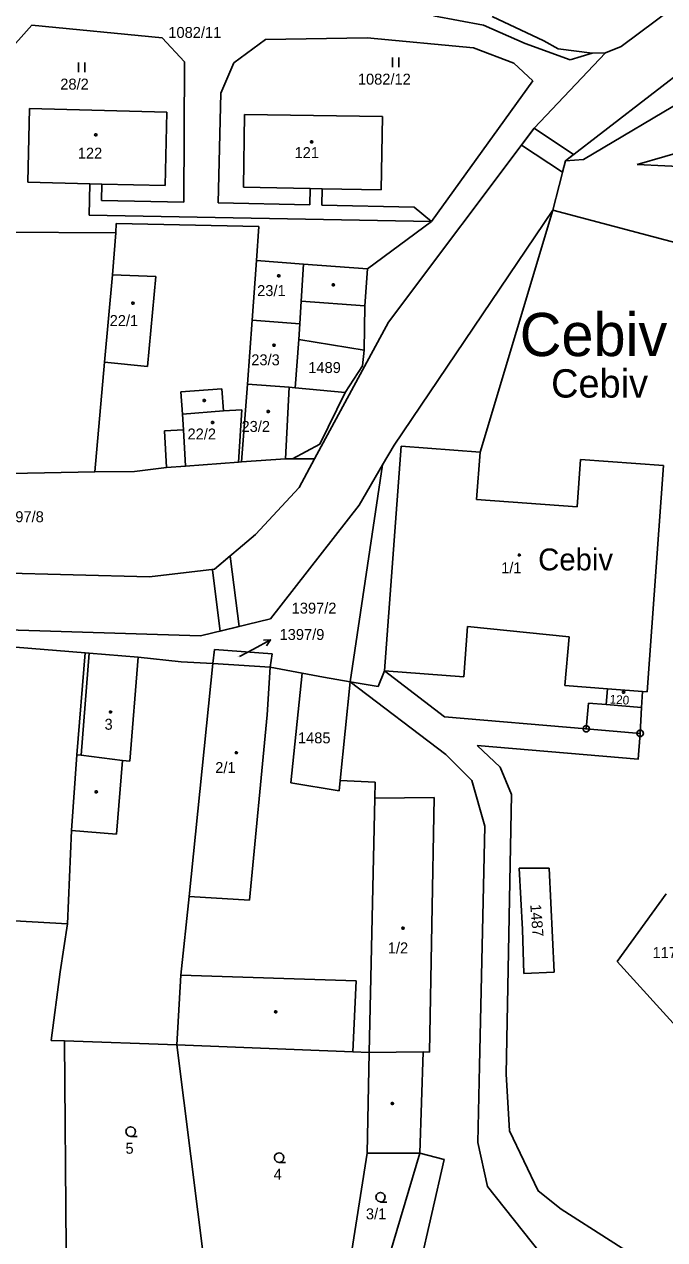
# Model space of a CAD drawing. Extents: x -850689 to -847910, y -1058374 to -1054747.
# Drawn here: x -849425.6 to -849326.1, y -1056444.2 to -1056255.5 of the extents above; entities that cross this region are included whole.
import ezdxf

# ---------------------------------------------------------------- set-up
doc = ezdxf.new("R2010")
doc.units = 0
for name, color, linetype in [('KN_BREMENA', 7, 'Continuous'), ('KN_HRANICE', 7, 'Continuous'), ('KN_KULTURY', 7, 'Continuous'), ('KN_MEZNIKY', 7, 'Continuous'), ('KN_PARCELY', 7, 'Continuous'), ('KN_SLUCKY', 7, 'Continuous'), ('KN_STAVEBNI', 7, 'Continuous')]:
    doc.layers.add(name, color=color, linetype=linetype)

# ---------------------------------------------------------------- blocks, each defined once
blk = doc.blocks.new('304')
blk.add_lwpolyline([(0, 0), (-0.38, 0.1), (-0.65, 0.37), (-0.75, 0.74), (-0.65, 1.11), (-0.38, 1.38), (-0.01, 1.48), (0.36, 1.38), (0.63, 1.11), (0.73, 0.73), (0.63, 0.35), (0.36, 0.08), (-0.02, -0.02), (0.98, -0.02)])
blk = doc.blocks.new('306')
for p, q in [((-0.5, 1.5), (-0.5, 0)), ((0.5, 0), (0.5, 1.5))]:
    blk.add_line(p, q)
blk = doc.blocks.new('10292')
blk.add_line((0, 3), (0, 0))
blk.add_lwpolyline([(-0.5, 2), (0, 3), (0.5, 2)])
blk = doc.blocks.new('402')
blk.add_lwpolyline([(0.09, 0.15), (0.18, 0), (0.09, -0.15), (-0.09, -0.15), (-0.18, 0), (-0.09, 0.15), (0.09, 0.15)])
blk = doc.blocks.new('105')
blk.add_line((-0.12, 0), (0.12, 0))
blk.add_lwpolyline([(0.15, 0.48), (0.4, 0.3), (0.5, 0.01), (0.4, -0.28), (0.15, -0.46), (-0.16, -0.46), (-0.41, -0.28), (-0.51, 0.01), (-0.41, 0.3), (-0.16, 0.48), (0.15, 0.48)])

msp = doc.modelspace()

# ---------------------------------------------------------------- linework, layer by layer
at = {"layer": 'KN_BREMENA'}
for points in [[(-849342, -1056278.44), (-849348.38, -1056274.23), (-849346.41, -1056271.62), (-849340.27, -1056275.67), (-849341.54, -1056276.65)], [(-849395.16, -1056349.69), (-849396.35, -1056340.23), (-849396.37, -1056340.1), (-849396.03, -1056340.06), (-849393.6, -1056338), (-849393.54, -1056338.48), (-849392.22, -1056348.98)]]:
    msp.add_lwpolyline(points, close=True, dxfattribs=at)
for points in [[(-849354.04, -1056379.97), (-849356.06, -1056372.86), (-849360.12, -1056368.85), (-849374.96, -1056357.55), (-849370.64, -1056358.28), (-849369.64, -1056355.88), (-849360.34, -1056362.98)], [(-849360.34, -1056362.98), (-849338.31, -1056364.85), (-849329.95, -1056365.57), (-849330.23, -1056369.56), (-849355.23, -1056367.43)], [(-849355.23, -1056367.43), (-849351.69, -1056370.82), (-849349.93, -1056375.07), (-849350.77, -1056418.49), (-849350.24, -1056427.3), (-849345.77, -1056436.61), (-849342.23, -1056439.43), (-849327.01, -1056449.14), (-849298.02, -1056468.19), (-849284.6, -1056463.96), (-849270.77, -1056447.7), (-849287.91, -1056435.18), (-849282.02, -1056427.2), (-849264.01, -1056440.34), (-849244.44, -1056411.59), (-849258.75, -1056401.09), (-849252.32, -1056392.28), (-849210.21, -1056427.21)], [(-849305.2, -1056487.17), (-849298.59, -1056476.85), (-849345.45, -1056446.21), (-849353.67, -1056435.91), (-849355.13, -1056429.06), (-849354.9, -1056417.2), (-849354.04, -1056379.97)]]:
    msp.add_lwpolyline(points, dxfattribs=at)
at = {"layer": 'KN_HRANICE'}
for p, q in [((-849324.78, -1056252.85), (-849332.91, -1056258.92)), ((-849362.03, -1056254.15), (-849354.27, -1056255.62)), ((-849344.89, -1056258.04), (-849352.94, -1056254.24)), ((-849424.4, -1056255.6), (-849428.61, -1056260.33)), ((-849404.18, -1056257.55), (-849424.4, -1056255.6)), ((-849354.27, -1056255.62), (-849347.82, -1056258.48)), ((-849400.7, -1056261.28), (-849404.18, -1056257.55)), ((-849388.12, -1056257.84), (-849393.05, -1056261.45)), ((-849372.35, -1056257.55), (-849388.12, -1056257.84)), ((-849355.83, -1056259.12), (-849372.35, -1056257.55)), ((-849349.55, -1056261.51), (-849355.83, -1056259.12)), ((-849347.82, -1056258.48), (-849340.83, -1056261.01)), ((-849342.67, -1056259.27), (-849344.89, -1056258.04)), ((-849335.32, -1056259.89), (-849332.91, -1056258.92)), ((-849335.32, -1056259.89), (-849346.41, -1056271.62)), ((-849337.4, -1056259.96), (-849342.67, -1056259.27)), ((-849340.83, -1056261.01), (-849337.4, -1056259.96)), ((-849338.74, -1056276.48), (-849311.64, -1056260.39)), ((-849335.32, -1056259.89), (-849337.4, -1056259.96)), ((-849400.7, -1056261.28), (-849400.81, -1056283.1)), ((-849393.05, -1056261.45), (-849395.08, -1056266.18)), ((-849346.61, -1056264.23), (-849349.55, -1056261.51)), ((-849341.54, -1056276.65), (-849321.82, -1056261.46)), ((-849346.61, -1056264.23), (-849362.36, -1056286.11)), ((-849395.08, -1056266.18), (-849395.45, -1056283.21)), ((-849425.04, -1056279.98), (-849424.78, -1056268.57)), ((-849424.78, -1056268.57), (-849403.43, -1056269.1)), ((-849403.43, -1056269.1), (-849403.71, -1056280.52)), ((-849391.56, -1056280.75), (-849391.39, -1056269.46)), ((-849391.39, -1056269.46), (-849369.95, -1056269.77)), ((-849369.95, -1056269.77), (-849370.17, -1056281.18)), ((-849330.43, -1056277.22), (-849303.93, -1056269.58)), ((-849346.41, -1056271.62), (-849369.03, -1056301.74)), ((-849341.54, -1056276.65), (-849343.49, -1056284.33)), ((-849341.54, -1056276.65), (-849338.74, -1056276.48)), ((-849330.43, -1056277.22), (-849321.06, -1056277.69)), ((-849415.41, -1056280.22), (-849425.04, -1056279.98)), ((-849415.48, -1056285.11), (-849415.41, -1056280.22)), ((-849413.55, -1056280.27), (-849415.41, -1056280.22)), ((-849413.61, -1056282.82), (-849413.55, -1056280.27)), ((-849403.71, -1056280.52), (-849413.55, -1056280.27)), ((-849381.2, -1056280.96), (-849391.56, -1056280.75)), ((-849381.26, -1056283.52), (-849381.2, -1056280.96)), ((-849379.31, -1056281), (-849381.2, -1056280.96)), ((-849379.36, -1056283.57), (-849379.31, -1056281)), ((-849370.17, -1056281.18), (-849379.31, -1056281)), ((-849413.61, -1056282.82), (-849400.81, -1056283.1)), ((-849395.45, -1056283.21), (-849381.26, -1056283.52)), ((-849379.36, -1056283.57), (-849365.06, -1056283.87)), ((-849415.48, -1056285.11), (-849362.36, -1056286.11)), ((-849368.16, -1056320.82), (-849343.49, -1056284.33)), ((-849365.06, -1056283.87), (-849362.36, -1056286.11)), ((-849343.49, -1056284.33), (-849354.8, -1056321.89)), ((-849299.89, -1056295.86), (-849343.49, -1056284.33)), ((-849411.31, -1056286.39), (-849411.38, -1056287.83)), ((-849389.17, -1056286.88), (-849411.31, -1056286.39)), ((-849389.17, -1056286.88), (-849389.51, -1056292.14)), ((-849372.28, -1056293.44), (-849362.36, -1056286.11)), ((-849429.11, -1056287.73), (-849411.38, -1056287.83)), ((-849411.38, -1056287.83), (-849411.89, -1056294.39)), ((-849389.51, -1056292.14), (-849390.2, -1056301.43)), ((-849382.2, -1056292.69), (-849389.51, -1056292.14)), ((-849372.28, -1056293.44), (-849382.2, -1056292.69)), ((-849411.89, -1056294.39), (-849413.11, -1056307.95)), ((-849372.68, -1056299.17), (-849372.28, -1056293.44)), ((-849372.79, -1056306.07), (-849372.68, -1056299.17)), ((-849390.2, -1056301.43), (-849390.94, -1056311.34)), ((-849390.2, -1056301.43), (-849382.78, -1056301.99)), ((-849382.78, -1056301.99), (-849382.93, -1056304.4)), ((-849369.03, -1056301.74), (-849380.49, -1056322.95)), ((-849382.93, -1056304.4), (-849383.52, -1056311.92)), ((-849372.79, -1056306.07), (-849382.93, -1056304.4)), ((-849373.05, -1056308.51), (-849372.79, -1056306.07)), ((-849413.11, -1056307.95), (-849414.63, -1056324.97)), ((-849375.73, -1056312.66), (-849373.05, -1056308.51)), ((-849390.94, -1056311.34), (-849391.84, -1056323.41)), ((-849390.94, -1056311.34), (-849384.46, -1056311.82)), ((-849383.52, -1056311.92), (-849384.46, -1056311.82)), ((-849383.52, -1056311.92), (-849375.73, -1056312.66)), ((-849394.9, -1056312.07), (-849401.27, -1056312.56)), ((-849401.27, -1056312.56), (-849401.01, -1056315.99)), ((-849394.9, -1056312.07), (-849394.64, -1056315.5)), ((-849379.69, -1056320.65), (-849375.73, -1056312.66)), ((-849394.64, -1056315.5), (-849391.81, -1056315.32)), ((-849392.34, -1056323.46), (-849391.81, -1056315.32)), ((-849401.01, -1056315.99), (-849400.86, -1056318.43)), ((-849400.86, -1056318.43), (-849403.83, -1056318.61)), ((-849403.52, -1056324.31), (-849403.83, -1056318.61)), ((-849379.69, -1056320.65), (-849383.92, -1056322.95)), ((-849369.95, -1056323.89), (-849368.16, -1056320.82)), ((-849385.02, -1056322.95), (-849391.84, -1056323.41)), ((-849383.92, -1056322.95), (-849385.02, -1056322.95)), ((-849380.49, -1056322.95), (-849383.92, -1056322.95)), ((-849382.88, -1056327.38), (-849380.49, -1056322.95)), ((-849355.34, -1056329.26), (-849354.8, -1056321.89)), ((-849339.2, -1056323.03), (-849339.74, -1056330.4)), ((-849326.3, -1056323.97), (-849339.2, -1056323.03)), ((-849427.65, -1056325.24), (-849414.63, -1056324.97)), ((-849414.63, -1056324.97), (-849408.44, -1056324.93)), ((-849408.44, -1056324.93), (-849403.52, -1056324.31)), ((-849403.52, -1056324.31), (-849400.53, -1056324.08)), ((-849400.53, -1056324.08), (-849392.34, -1056323.46)), ((-849392.34, -1056323.46), (-849391.84, -1056323.41)), ((-849374.96, -1056357.55), (-849369.95, -1056323.89)), ((-849373.58, -1056330.12), (-849369.95, -1056323.89)), ((-849328.87, -1056359.11), (-849326.3, -1056323.97)), ((-849382.88, -1056327.38), (-849389.7, -1056334.7)), ((-849387.32, -1056347.8), (-849373.58, -1056330.12)), ((-849339.74, -1056330.4), (-849355.34, -1056329.26)), ((-849389.7, -1056334.7), (-849396.03, -1056340.06)), ((-849406.11, -1056341.28), (-849532.06, -1056337.93)), ((-849396.03, -1056340.06), (-849406.11, -1056341.28)), ((-849398.2, -1056350.42), (-849387.32, -1056347.8)), ((-849457.69, -1056348.54), (-849398.2, -1056350.42)), ((-849357.35, -1056356.77), (-849356.75, -1056348.99)), ((-849356.75, -1056348.99), (-849340.97, -1056350.6)), ((-849340.97, -1056350.6), (-849341.66, -1056358.11)), ((-849416.15, -1056353.07), (-849426.94, -1056352.2)), ((-849417.42, -1056368.92), (-849416.15, -1056353.07)), ((-849415.5, -1056353.12), (-849416.15, -1056353.07)), ((-849415.5, -1056353.12), (-849407.89, -1056353.73)), ((-849396.05, -1056352.55), (-849396.28, -1056354.7)), ((-849387.11, -1056353.22), (-849396.05, -1056352.55)), ((-849387.38, -1056355.27), (-849387.11, -1056353.22)), ((-849407.89, -1056353.73), (-849401.22, -1056354.48)), ((-849401.22, -1056354.48), (-849397.3, -1056354.68)), ((-849400, -1056390.91), (-849396.28, -1056354.7)), ((-849397.3, -1056354.68), (-849396.28, -1056354.7)), ((-849396.28, -1056354.7), (-849387.38, -1056355.27)), ((-849382.44, -1056356.21), (-849387.38, -1056355.27)), ((-849384.19, -1056373.23), (-849382.44, -1056356.21)), ((-849379.1, -1056356.85), (-849382.44, -1056356.21)), ((-849379.1, -1056356.85), (-849374.96, -1056357.55)), ((-849369.64, -1056355.88), (-849370.64, -1056358.28)), ((-849369.64, -1056355.88), (-849357.35, -1056356.77)), ((-849376.53, -1056372.86), (-849374.96, -1056357.55)), ((-849374.96, -1056357.55), (-849370.64, -1056358.28)), ((-849341.66, -1056358.11), (-849335.01, -1056358.63)), ((-849335.2, -1056361.09), (-849335.01, -1056358.63)), ((-849335.01, -1056358.63), (-849329.56, -1056359.06)), ((-849329.56, -1056359.06), (-849329.72, -1056361.56)), ((-849329.56, -1056359.06), (-849328.87, -1056359.11)), ((-849338.31, -1056364.85), (-849337.97, -1056360.86)), ((-849337.97, -1056360.86), (-849335.2, -1056361.09)), ((-849329.72, -1056361.56), (-849329.95, -1056365.57)), ((-849329.95, -1056365.57), (-849338.31, -1056364.85)), ((-849417.42, -1056368.92), (-849418.27, -1056380.63)), ((-849384.19, -1056373.23), (-849376.7, -1056374.49)), ((-849376.7, -1056374.49), (-849376.53, -1056372.86)), ((-849376.53, -1056372.86), (-849371.1, -1056373.16)), ((-849371.1, -1056373.16), (-849371.15, -1056375.6)), ((-849371.15, -1056375.6), (-849372, -1056415.1)), ((-849418.85, -1056395.14), (-849418.27, -1056380.63)), ((-849348.73, -1056386.51), (-849348.23, -1056396.03)), ((-849348.73, -1056386.51), (-849344.08, -1056386.51)), ((-849344.08, -1056386.51), (-849343.29, -1056402.63)), ((-849401.25, -1056403.09), (-849400, -1056390.91)), ((-849325.93, -1056390.5), (-849333.53, -1056401)), ((-849434.1, -1056394.27), (-849418.85, -1056395.14)), ((-849420.01, -1056402.58), (-849418.85, -1056395.14)), ((-849348.23, -1056396.03), (-849348, -1056402.87)), ((-849333.53, -1056401), (-849323.3, -1056412.23)), ((-849421.41, -1056413.23), (-849420.01, -1056402.58)), ((-849401.89, -1056413.93), (-849401.25, -1056403.09)), ((-849348, -1056402.87), (-849343.29, -1056402.63)), ((-849419.34, -1056413.3), (-849421.41, -1056413.23)), ((-849419.09, -1056445.59), (-849419.34, -1056413.3)), ((-849419.34, -1056413.3), (-849401.89, -1056413.93)), ((-849401.89, -1056413.93), (-849374.54, -1056415)), ((-849401.89, -1056413.93), (-849397.43, -1056449.45)), ((-849374.54, -1056415), (-849372, -1056415.1)), ((-849372, -1056415.1), (-849372.33, -1056430.72)), ((-849375.87, -1056453.3), (-849372.33, -1056430.72)), ((-849364.14, -1056430.75), (-849372.33, -1056430.72)), ((-849364.14, -1056430.75), (-849371.16, -1056454.14)), ((-849364.14, -1056430.75), (-849360.36, -1056431.7)), ((-849360.36, -1056431.7), (-849366.02, -1056456.29))]:
    msp.add_line(p, q, dxfattribs=at)
at = {"layer": 'KN_PARCELY'}
msp.add_line((-849392.18, -1056353.64), (-849389.98, -1056352.47), dxfattribs=at)
at = {"layer": 'KN_SLUCKY'}
for p, q in [((-849382.2, -1056292.69), (-849382.56, -1056298.48)), ((-849405.13, -1056294.64), (-849411.89, -1056294.39)), ((-849405.13, -1056294.64), (-849406.45, -1056308.58)), ((-849382.56, -1056298.48), (-849382.78, -1056301.99)), ((-849372.68, -1056299.17), (-849382.56, -1056298.48)), ((-849406.45, -1056308.58), (-849413.11, -1056307.95)), ((-849384.46, -1056311.82), (-849385.02, -1056322.95)), ((-849401.01, -1056315.99), (-849394.64, -1056315.5)), ((-849400.86, -1056318.43), (-849400.53, -1056324.08)), ((-849367.07, -1056320.99), (-849369.64, -1056355.88)), ((-849354.8, -1056321.89), (-849367.07, -1056320.99)), ((-849416.77, -1056368.97), (-849415.5, -1056353.12)), ((-849407.89, -1056353.73), (-849409.18, -1056369.88)), ((-849387.38, -1056355.27), (-849387.87, -1056362.69)), ((-849387.87, -1056362.69), (-849390.59, -1056391.46)), ((-849335.2, -1056361.09), (-849329.72, -1056361.56)), ((-849417.42, -1056368.92), (-849416.77, -1056368.97)), ((-849416.77, -1056368.97), (-849410.33, -1056369.79)), ((-849411.25, -1056381.2), (-849410.33, -1056369.79)), ((-849410.33, -1056369.79), (-849409.18, -1056369.88)), ((-849371.15, -1056375.6), (-849361.91, -1056375.5)), ((-849361.91, -1056375.5), (-849362.64, -1056415.04)), ((-849418.27, -1056380.63), (-849411.25, -1056381.2)), ((-849400, -1056390.91), (-849390.59, -1056391.46)), ((-849401.25, -1056403.09), (-849374.04, -1056404)), ((-849374.04, -1056404), (-849374.54, -1056415)), ((-849372, -1056415.1), (-849363.62, -1056415.02)), ((-849363.62, -1056415.02), (-849364.14, -1056430.75)), ((-849362.64, -1056415.04), (-849363.62, -1056415.02))]:
    msp.add_line(p, q, dxfattribs=at)
at = {"layer": 'KN_STAVEBNI'}
for p, q in [((-849425.04, -1056279.98), (-849424.78, -1056268.57)), ((-849424.78, -1056268.57), (-849403.43, -1056269.1)), ((-849403.43, -1056269.1), (-849403.71, -1056280.52)), ((-849391.56, -1056280.75), (-849391.39, -1056269.46)), ((-849391.39, -1056269.46), (-849369.95, -1056269.77)), ((-849369.95, -1056269.77), (-849370.17, -1056281.18)), ((-849415.41, -1056280.22), (-849425.04, -1056279.98)), ((-849413.55, -1056280.27), (-849415.41, -1056280.22)), ((-849403.71, -1056280.52), (-849413.55, -1056280.27)), ((-849381.2, -1056280.96), (-849391.56, -1056280.75)), ((-849379.31, -1056281), (-849381.2, -1056280.96)), ((-849370.17, -1056281.18), (-849379.31, -1056281)), ((-849389.51, -1056292.14), (-849390.2, -1056301.43)), ((-849382.2, -1056292.69), (-849389.51, -1056292.14)), ((-849382.2, -1056292.69), (-849382.56, -1056298.48)), ((-849411.89, -1056294.39), (-849413.11, -1056307.95)), ((-849405.13, -1056294.64), (-849411.89, -1056294.39)), ((-849405.13, -1056294.64), (-849406.45, -1056308.58)), ((-849382.56, -1056298.48), (-849382.78, -1056301.99)), ((-849390.2, -1056301.43), (-849390.94, -1056311.34)), ((-849390.2, -1056301.43), (-849382.78, -1056301.99)), ((-849390.2, -1056301.43), (-849382.78, -1056301.99)), ((-849382.78, -1056301.99), (-849382.93, -1056304.4)), ((-849382.93, -1056304.4), (-849383.52, -1056311.92)), ((-849406.45, -1056308.58), (-849413.11, -1056307.95)), ((-849390.94, -1056311.34), (-849391.84, -1056323.41)), ((-849390.94, -1056311.34), (-849384.46, -1056311.82)), ((-849390.94, -1056311.34), (-849384.46, -1056311.82)), ((-849384.46, -1056311.82), (-849385.02, -1056322.95)), ((-849383.52, -1056311.92), (-849384.46, -1056311.82)), ((-849401.01, -1056315.99), (-849394.64, -1056315.5)), ((-849394.64, -1056315.5), (-849391.81, -1056315.32)), ((-849392.34, -1056323.46), (-849391.81, -1056315.32)), ((-849401.01, -1056315.99), (-849400.86, -1056318.43)), ((-849400.86, -1056318.43), (-849400.53, -1056324.08)), ((-849367.07, -1056320.99), (-849369.64, -1056355.88)), ((-849354.8, -1056321.89), (-849367.07, -1056320.99)), ((-849385.02, -1056322.95), (-849391.84, -1056323.41)), ((-849355.34, -1056329.26), (-849354.8, -1056321.89)), ((-849339.2, -1056323.03), (-849339.74, -1056330.4)), ((-849326.3, -1056323.97), (-849339.2, -1056323.03)), ((-849400.53, -1056324.08), (-849392.34, -1056323.46)), ((-849328.87, -1056359.11), (-849326.3, -1056323.97)), ((-849339.74, -1056330.4), (-849355.34, -1056329.26)), ((-849357.35, -1056356.77), (-849356.75, -1056348.99)), ((-849356.75, -1056348.99), (-849340.97, -1056350.6)), ((-849340.97, -1056350.6), (-849341.66, -1056358.11)), ((-849416.77, -1056368.97), (-849415.5, -1056353.12)), ((-849415.5, -1056353.12), (-849407.89, -1056353.73)), ((-849407.89, -1056353.73), (-849409.18, -1056369.88)), ((-849400, -1056390.91), (-849396.28, -1056354.7)), ((-849396.28, -1056354.7), (-849387.38, -1056355.27)), ((-849387.38, -1056355.27), (-849387.87, -1056362.69)), ((-849369.64, -1056355.88), (-849357.35, -1056356.77)), ((-849341.66, -1056358.11), (-849335.01, -1056358.63)), ((-849335.2, -1056361.09), (-849335.01, -1056358.63)), ((-849335.01, -1056358.63), (-849329.56, -1056359.06)), ((-849335.01, -1056358.63), (-849329.56, -1056359.06)), ((-849329.56, -1056359.06), (-849329.72, -1056361.56)), ((-849329.56, -1056359.06), (-849328.87, -1056359.11)), ((-849387.87, -1056362.69), (-849390.59, -1056391.46)), ((-849335.2, -1056361.09), (-849329.72, -1056361.56)), ((-849416.77, -1056368.97), (-849410.33, -1056369.79)), ((-849410.33, -1056369.79), (-849409.18, -1056369.88)), ((-849371.15, -1056375.6), (-849372, -1056415.1)), ((-849371.15, -1056375.6), (-849361.91, -1056375.5)), ((-849361.91, -1056375.5), (-849362.64, -1056415.04)), ((-849400, -1056390.91), (-849390.59, -1056391.46)), ((-849325.93, -1056390.5), (-849333.53, -1056401)), ((-849333.53, -1056401), (-849323.3, -1056412.23)), ((-849372, -1056415.1), (-849363.62, -1056415.02)), ((-849362.64, -1056415.04), (-849363.62, -1056415.02))]:
    msp.add_line(p, q, dxfattribs=at)

# ---------------------------------------------------------------- block references
at = {"layer": 'KN_KULTURY'}
for name, p in [('306', (-849367.91, -1056262.14)), ('306', (-849416.67, -1056262.91)), ('402', (-849414.48, -1056272.63)), ('402', (-849380.96, -1056273.73)), ('402', (-849386.06, -1056294.51)), ('402', (-849377.59, -1056295.92)), ('402', (-849408.72, -1056298.76)), ('402', (-849386.81, -1056305.3)), ('402', (-849397.64, -1056313.88)), ('402', (-849387.7, -1056315.61)), ('402', (-849396.34, -1056317.3)), ('402', (-849348.72, -1056337.87)), ('402', (-849332.52, -1056359.18)), ('402', (-849412.18, -1056362.25)), ('402', (-849392.64, -1056368.56)), ('402', (-849414.41, -1056374.66)), ('402', (-849366.77, -1056395.79)), ('402', (-849386.53, -1056408.79)), ('402', (-849368.42, -1056423.03)), ('304', (-849409.05, -1056428.13)), ('304', (-849386, -1056432.17)), ('304', (-849370.26, -1056438.31))]:
    msp.add_blockref(name, p, dxfattribs=at)
at = {"layer": 'KN_MEZNIKY'}
for p in [(-849338.31, -1056364.85), (-849329.95, -1056365.57)]:
    msp.add_blockref('105', p, dxfattribs=at)
at = {"layer": 'KN_PARCELY', "rotation": -62.00465099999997}
msp.add_blockref('10292', (-849389.98, -1056352.47), dxfattribs=at)

# ---------------------------------------------------------------- texts
at = {"layer": 'KN_PARCELY'}
for s, height, p in [('1082/11', 1.7, (-849403.21, -1056257.59)), ('28/2', 1.7, (-849419.99, -1056265.61)), ('1082/12', 1.7, (-849373.78, -1056264.84)), ('122', 1.7, (-849417.27, -1056276.33)), ('121', 1.7, (-849383.61, -1056276.25)), ('23/1', 1.7, (-849389.42, -1056297.67)), ('22/1', 1.7, (-849412.32, -1056302.32)), ('Cebiv', 6.7, (-849348.64, -1056306.99)), ('23/3', 1.7, (-849390.33, -1056308.42)), ('1489', 1.7, (-849381.48, -1056309.62)), ('Cebiv', 4.4, (-849343.77, -1056313.43)), ('23/2', 1.7, (-849391.85, -1056318.76)), ('22/2', 1.7, (-849400.23, -1056319.93)), ('1397/8', 1.7, (-849429.5, -1056332.78)), ('Cebiv', 3.4, (-849345.78, -1056340.26)), ('1/1', 1.7, (-849351.53, -1056340.71)), ('1397/2', 1.7, (-849384.06, -1056346.97)), ('1397/9', 1.7, (-849385.94, -1056351.06)), ('1397/9', 0.1, (-849392.48, -1056353.64)), ('3', 1.7, (-849413.12, -1056365)), ('1485', 1.7, (-849383.08, -1056367.11)), ('2/1', 1.7, (-849395.93, -1056371.72)), ('1/2', 1.7, (-849369.13, -1056399.72)), ('117/1', 1.7, (-849328.03, -1056400.45)), ('5', 1.7, (-849409.86, -1056430.83)), ('4', 1.7, (-849386.85, -1056434.87)), ('3/1', 1.7, (-849372.53, -1056441.01))]:
    msp.add_text(s, height=height, dxfattribs=at).set_placement(p)
for s, height, rotation, p in [('120', 1.36, 356.151, (-849334.72, -1056360.91)), ('1487', 1.7, 274.389, (-849347.02, -1056392.15))]:
    msp.add_text(s, height=height, rotation=rotation, dxfattribs=at).set_placement(p)

doc.saveas('drawing.dxf')
